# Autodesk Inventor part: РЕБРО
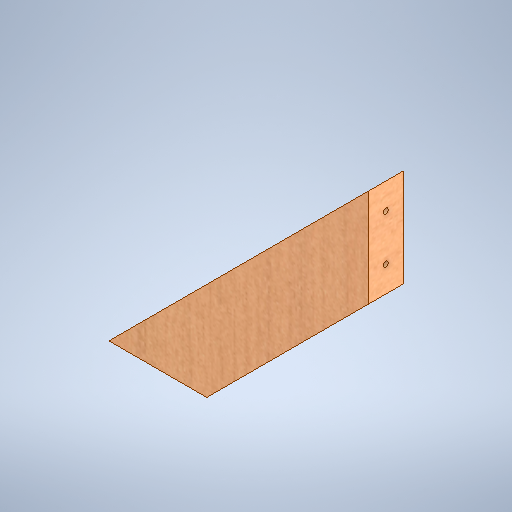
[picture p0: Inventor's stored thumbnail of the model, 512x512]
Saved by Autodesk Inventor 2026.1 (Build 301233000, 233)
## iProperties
Created: 2025-12
Part Number: РЕБРО
Material: Типовые
Document SubType Name: Modeling
Designer: Yury Melnikov
Density: 1 g/cm^3
Appearance: Вишневое дерево — натуральный — со слабым глянцем
Author: Yury Melnikov
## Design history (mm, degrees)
sketch "Эскиз1"
  geometry: L1 (-150, 0)-(0, 0); L2 (0, 0)-(0, 150); L3 (0, 150)-(-150, 0); L4 (-93.431, 0)-(0, 93.431); L5 (0, 150)-(0, 93.431); L6 (-150, 0)-(-93.431, 0)
  constraints: 12 end point, 2 point on line, 1 collinear, 1 horizontal, 1 parallel, 1 perpendicular, 1 vertical
  dimensions: "d0" = 150 distance of L1.start L1.end; "d1" = 150 distance of L1.end L2.end; "d2" = 40 distance between parallel lines of L4 L3
extrude "Выдавливание1" new body sketch "Эскиз1" distance "d3" = 20; taper "d4" = 0 deg
sketch "Эскиз2"
  geometry: L1 (0, 0)-(0, 56.569) reference; L2 (0, 56.569)-(-20, 56.569) reference; L3 (-20, 0)-(-20, 56.569) reference; L4 (0, 0)-(-20, 0) reference; C1 r 1.5 at (-10, 41.569); C2 r 1.5 at (-10, 15); 2 further points
  constraints: 2 centre point, 2 vertical alignment, 1 equal radius, 1 midpoint
  dimensions: "d5" = 3 diameter of C1; "d6" = 15 distance from line of L2 C1.centre (= d7); "d7" = 15 distance from line of L4 C2.centre
extrude "Выдавливание2" cut sketch "Эскиз2" distance "d8" = 5; taper "d9" = 0 deg
sketch "Эскиз3"
  geometry: L1 (56.569, 0)-(56.569, 20) reference; L2 (0, 0)-(0, 20) reference; C1 r 1.5 at (15, 10); C2 r 1.5 at (41.569, 10); 2 further points
  constraints: 2 centre point, 2 horizontal alignment, 1 equal radius, 1 midpoint
  dimensions: "d13" = 15 distance from line of L1 C2.centre; "d14" = 15 distance from line of L2 C1.centre (= d13); "d15" = 3 diameter of C2
extrude "Выдавливание3" cut sketch "Эскиз3" distance "d16" = 5; taper "d17" = 0 deg
sketch "Эскиз4"
  geometry: L1 (150, 0)-(150, 20) reference; C1 r 1.5 at (15, 10) reference; C2 r 1.5 at (41.569, 10) reference
  dimensions: "d18" = 135 distance from line of C1.centre L1 (derived); "d19" = 26.56854 distance of C1.centre C2.centre (derived)
node "Твердое тело1"
node "Спроецированная петля1"
